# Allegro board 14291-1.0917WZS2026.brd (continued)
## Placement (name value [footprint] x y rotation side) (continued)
C8304  SC10U10V5KX-2GP  [C805H54]  168.09 127.24 180 bottom
C8305  SC1U10V2KX-1GP  [C402H22]  174.03 133.2 180 bottom
C8306  SC470P50V2KX-3GP  [C402H22]  170.86 128.9 0 top
C8307  SC1U10V2KX-1GP  [C402H22]  168.85 133.33 180 bottom
C9101  SC4D7U6D3V3KX-GP  [C603H36]  170.88 21.28 0 bottom
C9102  SCD1U16V2KX-3GP  [C402H22]  171.42 19.6 270 bottom
C9103  SCD1U16V2KX-3GP  [C402H22]  163.57 18.17 90 bottom
C9104  SCD1U16V2KX-3GP  [C402H22]  168.17 30.71 0 bottom
C9105  SCD1U16V2KX-3GP  [C402H22]  160.88 28.67 180 bottom
C9106  SC4D7U6D3V3KX-GP  [C603H36]  161.95 28.56 180 bottom
C9201  SCD1U16V2KX-3GP  [C402H22]  182.48 124.94 0 top
C9202  SC1U10V2KX-1GP  [C402H22]  181.57 124.94 0 top
CPU1  SKYLAKE-U-GP  [BGA1356M4224-U2H52]  115.4 83.77 0 bottom
D502  AZ5725-01FDR7G-GP  [SOD882-10D6-1H20]  148.26 66.99 180 top
D1217  AZ5725-01FDR7G-GP  [SOD882-10D6-1H20]  72.62 30 0 top
D1319  AZ5725-01FDR7G-GP  [SOD882-10D6-1H20]  86.51 17.53 0 top
D1701  1N4148WS-7-F-GP  [SOD323AKH42]  150.31 43.64 270 top
D1702  BAW56-9-GP  [SOT-23-10H44]  153.23 71.02 90 top
D1703  RB751V-40H-GP  [SOD323AKH38]  161.36 66.26 90 top
D2402  RB751V-40H-GP  [SOD323AKH38]  184.48 83.7 180 bottom
D2403  RB751V-40H-GP  [SOD323AKH38]  186.58 85.35 0 bottom
D2405  RB751V-40H-GP  [SOD323AKH38]  167.65 60.48 270 top
D2501  BAS40C-2-GP  [SOT-23-9H44]  51 9.25 180 bottom
D2601  RB551V30-GP  [SOD323AKH38]  97.18 134.35 180 top
D2701  BAT54C-7-F-3-GP  [SOT23-2D4-312H48]  35.09 22.61 90 top
D4001  RB751V-40H-GP  [SOD323AKH38]  30.68 58.17 180 top
D4002  BAS16-6-GP  [SOT23-2D4-312H44]  123.44 150.27 270 top
D4004  1N4148WS-7-F-GP  [SOD323AKH42]  166.2 118.53 270 bottom
D4005  1N4148WS-7-F-GP  [SOD323AKH42]  157.15 113.42 270 bottom
D4304  LBAV99LT1G-1-GP  [SOT23-2D4-312H44]  152.78 168.94 0 top
D4305  LBAV99LT1G-1-GP  [SOT23-2D4-312H44]  156.84 168.94 0 top
D4306  LBAV99LT1G-1-GP  [SOT23-2D4-312H44]  160.9 168.94 0 top
D5401  BAW56-9-GP  [SOT-23-10H44]  15.95 76.23 90 top
D5502  BAT54C-7-F-3-GP  [SOT23-2D4-312H48]  83.78 147.93 270 bottom
D5503  BAT54C-7-F-3-GP  [SOT23-2D4-312H48]  66.42 161.95 90 bottom
D7301  BAT54A-1-GP  [SOT23-2D4-312H44]  184.68 125.89 180 bottom
D7601  1SS400GPT-GP  [SOD723AKH27]  205.79 132.99 90 top
D7602  1SS400GPT-GP  [SOD723AKH27]  205.8 131.7 90 top
D8301  BAT54C-7-F-3-GP  [SOT23-2D4-312H48]  150.04 39.68 180 top
DB1  FOX-CON10-S1-GP  [HS81100]  164.97 33.94 180 bottom
DB2  ACES-CON4-37-GP  [88459-047N]  151.74 9.4 270 bottom
DB3  ACES-CON6-58-GP  [50696-00601-001]  157.09 11.93 180 bottom
DCIN1  ACES-CON6-63-GP  [50458-00601-W01]  91.4 166.77 180 top
DM1  DDR3-204P-252-GP-U  [DAN06-K4406-0103-U]  94.9 34.07 180 bottom
DM2  DDR3-204P-259-GP  [AS0A621-J4SB-7H]  109.4 20.87 0 bottom
EC1001  SC1U10V2KX-1GP  [C402H22]  121.72 14.23 0 top
EC1002  SCD1U25V2KX-GP  [C402H22]  108.97 38.57 0 top
EC1003  SC1U10V2KX-1GP  [C402H22]  111.72 38.59 0 top
EC1004  SC1U10V2KX-1GP  [C402H22]  107.63 29.25 180 top
EC1005  SCD1U25V2KX-GP  [C402H22]  109.52 29.24 180 top
EC1702  SC1KP50V2KX-1GP  [C402H22]  141.39 96.26 180 bottom
EC1703  SC1KP50V2KX-1GP  [C402H22]  156.1 73.6 180 bottom
EC1704  SC1KP50V2KX-1GP  [C402H22]  170.93 77.27 270 top
EC1706  SC1KP50V2KX-1GP  [C402H22]  135.3 102.07 0 bottom
EC1707  SCD1U16V2KX-3GP  [C402H22]  158.92 64.46 180 bottom
EC1708  SCD1U16V2KX-3GP  [C402H22]  96.11 99.06 270 bottom
EC1709  SCD1U16V2KX-3GP  [C402H22]  93 104.39 180 bottom
EC1710  SC22P50V2JN-4GP  [C402H22]  85.92 95.88 180 bottom
EC1711  SCD1U16V2KX-3GP  [C402H22]  149.88 71.64 0 bottom
EC1712  SCD1U16V2KX-3GP  [C402H22]  151.14 74.61 270 bottom
EC1713  SC22P50V2JN-4GP  [C402H22]  138.07 56.66 180 top
EC1801  SC10P50V2JN-4GP  [C402H22]  135.54 64.33 0 top
EC1802  SC10P50V2JN-4GP  [C402H22]  133.01 64.42 180 top
EC1803  SC4D7P50V2BN-GP  [C402H22]  128.11 64.34 180 top
EC1805  SCD1U16V2KX-3GP  [C402H22]  139.76 94.97 270 bottom
EC1806  SCD1U16V2KX-3GP  [C402H22]  134.92 61.46 180 top
EC1807  SCD1U16V2KX-3GP  [C402H22]  135.84 61.46 180 top
EC1808  SCD1U16V2KX-3GP  [C402H22]  138.59 60.14 0 top
EC1901  SC10P50V2JN-4GP  [C402H22]  136.95 45.67 90 bottom
EC1902  SCD1U16V2KX-3GP  [C402H22]  136.95 47.55 270 bottom
EC1903  SC1KP50V2KX-1GP  [C402H22]  135.46 98.71 0 bottom
EC2002  SC1KP50V2KX-1GP  [C402H22]  150.58 89.37 270 top
EC2401  SCD1U16V2KX-3GP  [C402H22]  192.84 72.77 270 top
EC2501  SC4D7P50V2BN-GP  [C402H22]  139.66 53.15 270 top
EC2502  SC4D7P50V2BN-GP  [C402H22]  147.49 54.32 270 bottom
EC2503  SC10P50V2JN-4GP  [C402H22]  139.02 55.35 270 top
EC2504  SC4D7P50V2BN-GP  [C402H22]  156.46 53.9 0 bottom
EC2505  SC10P50V2JN-4GP  [C402H22]  145.36 45.6 90 bottom
EC2506  SC4D7P50V2BN-GP  [C402H22]  145.36 43.9 90 bottom
EC2601  SCD1U16V2KX-3GP  [C402H22]  98.72 139.25 90 top
EC2602  SC10P50V2JN-4GP  [C402H22]  98.36 146.4 90 top
EC2701  SC10P50V2JN-4GP  [C402H22]  33.09 12.58 90 top
EC2703  SCD1U25V2KX-GP  [C402H22]  25 26.05 180 top
EC2704  SC1KP50V2KX-1GP  [C402H22]  16.23 19.71 270 top
EC2705  SCD1U25V2KX-GP  [C402H22]  29.33 27.08 0 bottom
EC2706  SC1KP50V2KX-1GP  [C402H22]  16.23 18.22 270 top
EC2707  SC1KP50V2KX-1GP  [C402H22]  24.89 27.08 0 bottom
EC2708  SC22P50V2JN-4GP  [C402H22]  36.44 19.77 0 top
EC2709  SC22P50V2JN-4GP  [C402H22]  35.94 17.17 180 top
EC2901  SC1KP50V2KX-1GP  [C402H22]  38.2 8.07 180 top
EC2902  SC1KP50V2KX-1GP  [C402H22]  38.41 10.14 0 top
EC2903  SC1KP50V2KX-1GP  [C402H22]  39.54 11.49 180 top
EC2904  SC1KP50V2KX-1GP  [C402H22]  40.36 14.42 0 top
EC2905  SC100P50V2JN-3GP  [C402H22]  21.28 11.01 0 top
EC2906  SC100P50V2JN-3GP  [C402H22]  16.66 11.1 90 top
EC2907  SC100P50V2JN-3GP  [C402H22]  18.21 21.14 90 top
EC2908  SC100P50V2JN-3GP  [C402H22]  17.93 19.61 90 top
EC3101  SC10P50V2JN-4GP  [C402H22]  36.88 175.67 0 top
EC3102  SC10P50V2JN-4GP  [C402H22]  36.88 173.97 180 top
EC3103  SC10P50V2JN-4GP  [C402H22]  35.31 174.34 0 top
EC3104  SC10P50V2JN-4GP  [C402H22]  35.31 172.67 180 top
EC3105  SC10P50V2JN-4GP  [C402H22]  36.83 173.9 0 bottom
EC3106  SC10P50V2JN-4GP  [C402H22]  36.82 175.59 180 bottom
EC3107  SC10P50V2JN-4GP  [C402H22]  35.43 175.8 0 bottom
EC3108  SC10P50V2JN-4GP  [C402H22]  35.43 177.58 180 bottom
EC4001  SCD1U16V2KX-3GP  [C402H22]  155.77 131.36 0 bottom
EC4301  SC10U25V5KX-GP  [C805H56]  90.9 159.15 90 top
EC4302  SCD1U25V2KX-GP  [C402H22]  90.95 157.81 90 top
EC4303  SCD1U25V2KX-GP  [C402H22]  84.49 154.39 270 top
EC4304  SCD1U25V2KX-GP  [C402H22]  96.88 159.41 180 top
EC4306  SC10P50V2JN-4GP  [C402H22]  152.65 166.4 90 top
EC4307  SCD1U25V2KX-GP  [C402H22]  164.21 171.48 90 top
EC4308  SC1U25V3KX-1-GP  [C603H36]  164.33 172.62 90 top
EC4309  SC10P50V2JN-4GP  [C402H22]  160.4 166.4 270 top
EC4310  SC10P50V2JN-4GP  [C402H22]  156.46 166.4 270 top
EC4311  SCD1U25V2KX-GP  [C402H22]  129.94 175.31 90 bottom
EC4312  SCD1U25V2KX-GP  [C402H22]  129.94 170.78 90 bottom
EC4313  SCD1U25V2KX-GP  [C402H22]  142.03 176.81 180 top
EC4314  SCD1U25V2KX-GP  [C402H22]  137.04 176.8 180 top
EC5101  SCD1U50V3KX-GP  [C603H36]  71.3 24.22 270 bottom
EC5102  SC1KP50V2KX-1GP  [C402H22]  100.88 14.25 0 top
EC5103  SC1KP50V2KX-1GP  [C402H22]  134.31 14.28 0 top
EC5301  SCD1U25V2KX-GP  [C402H22]  142.55 136.15 0 top
EC5501  SC6P50V2CN-1GP  [C402H22]  82.56 161.83 90 top
EC5502  SC6P50V2CN-1GP  [C402H22]  80.84 161.84 270 top
EC5503  SC33P50V2JN-3GP  [C402H22]  75.88 162.44 90 bottom
EC5504  SC10P50V2JN-4GP  [C402H22]  89.76 149.64 180 bottom
EC5505  SCD1U25V2KX-GP  [C402H22]  96.16 151.74 90 top
EC6001  SC1KP50V2KX-1GP  [C402H22]  184.83 28.61 90 bottom
EC6102  SC33P50V2JN-3GP  [C402H22]  165.3 65.66 270 bottom
EC6103  SC33P50V2JN-3GP  [C402H22]  163.6 65.66 90 bottom
EC6401  SC1KP50V2KX-1GP  [C402H22]  217.37 152.33 90 top
EC6402  SCD1U25V2KX-GP  [C402H22]  184.65 110.14 270 bottom
EC6403  SCD1U25V2KX-GP  [C402H22]  184.65 106.58 270 bottom
EC6405  SCD1U16V2KX-3GP  [C402H22]  218.82 151.44 270 top
EC6406  SCD1U16V2KX-3GP  [C402H22]  184.12 119.69 90 bottom
EC6407  SCD1U16V2KX-3GP  [C402H22]  183.45 121.48 180 bottom
EC6501  SC33P50V2JN-3GP  [C402H22]  52.19 78.52 0 top
EC6502  SC33P50V2JN-3GP  [C402H22]  49.65 74.32 0 top
EC6503  SC33P50V2JN-3GP  [C402H22]  52.19 80.29 180 top
EC6504  SC33P50V2JN-3GP  [C402H22]  49.65 76.1 180 top
EC6505  SC33P50V2JN-3GP  [C402H22]  49.78 69.88 0 top
EC6506  SC33P50V2JN-3GP  [C402H22]  49.78 71.66 180 top
EC6507  SCD1U16V2KX-3GP  [C402H22]  197.24 116.67 90 bottom
EC9201  SC22P50V2JN-4GP  [C402H22]  178.41 126.48 270 top
EC9202  SC22P50V2JN-4GP  [C402H22]  176.71 126.48 90 top
EC9701  SCD1U25V2KX-GP  [C402H22]  57.25 30.18 90 top
EC9702  SCD1U25V2KX-GP  [C402H22]  49.55 55.5 270 top
EC9703  SCD1U25V2KX-GP  [C402H22]  75.58 70.84 90 top
EC9704  SCD1U25V2KX-GP  [C402H22]  91.08 110.47 90 top
EC9705  SCD1U25V2KX-GP  [C402H22]  141.19 149.79 270 bottom
EC9706  SCD1U25V2KX-GP  [C402H22]  103.95 120.45 270 bottom
EC9707  SCD1U25V2KX-GP  [C402H22]  103.17 130.33 90 top
EC9708  SCD1U25V2KX-GP  [C402H22]  103.18 133.32 90 top
EC9709  SCD1U25V2KX-GP  [C402H22]  119.82 136.04 0 top
EC9710  SCD1U25V2KX-GP  [C402H22]  75.64 80.72 90 top
EC9711  SCD1U25V2KX-GP  [C402H22]  23.71 58.39 270 top
EC9712  SCD1U25V2KX-GP  [C402H22]  214.77 100.03 270 top
EC9713  SCD1U25V2KX-GP  [C402H22]  203.77 100.42 90 top
EC9714  SCD1U25V2KX-GP  [C402H22]  104 126.46 270 bottom
EC9715  SCD1U25V2KX-GP  [C402H22]  140.83 152.36 270 bottom
EC9716  SCD1U25V2KX-GP  [C402H22]  117.86 134.33 270 bottom
EC9717  SCD1U25V2KX-GP  [C402H22]  98.87 130.58 270 top
EC9718  SC1U10V2KX-1GP  [C402H22]  15.05 79.36 180 top
EC9719  SC1U10V2KX-1GP  [C402H22]  43.03 29.47 180 top
EC9720  SC1U10V2KX-1GP  [C402H22]  42.31 25.96 0 top
EC9721  SCD1U25V2KX-GP  [C402H22]  80.85 3.32 180 top
EC9722  SC1U10V2KX-1GP  [C402H22]  198.28 17.55 90 bottom
EC9723  SCD1U25V2KX-GP  [C402H22]  138.99 151.88 0 top
EC9724  SCD1U25V2KX-GP  [C402H22]  108.35 153.49 180 top
EC9725  SC1U10V2KX-1GP  [C402H22]  198.9 45.79 90 top
EC9726  SC1U25V3KX-1-GP  [C603H36]  109.4 153.14 180 top
EC9727  SC1U25V3KX-1-GP  [C603H36]  140.1 152.22 0 top
EC9728  SC1U25V3KX-1-GP  [C603H36]  98.84 131.65 270 top
EC9732  SC1U10V2KX-1GP  [C402H22]  37.28 30.92 90 bottom
EC9733  SC1U10V2KX-1GP  [C402H22]  57.29 11.35 270 bottom
EC9734  SC1U10V2KX-1GP  [C402H22]  148.56 7.52 0 bottom
EC9735  SCD1U25V2KX-GP  [C402H22]  134.75 152.38 180 top
EC9736  SC1U10V2KX-1GP  [C402H22]  36.19 25.9 90 top
EC9737  SC1U10V2KX-1GP  [C402H22]  33.17 75.77 0 bottom
EC9738  SC1U10V2KX-1GP  [C402H22]  67.51 85.75 0 bottom
EC9739  SCD1U25V2KX-GP  [C402H22]  16.28 23.25 270 top
EC9743  SCD1U25V2KX-GP  [C402H22]  16.25 23.27 90 bottom
EC9744  SCD1U25V2KX-GP  [C402H22]  16.63 15.52 0 bottom
EC9745  SC1KP50V2KX-1GP  [C402H22]  14.73 15.4 0 bottom
ED301  AZ5125-01H-R7G-GP  [SOD-523-4H28]  15.45 15.39 180 top
ED302  AZ5125-01H-R7G-GP  [SOD-523-4H28]  18.87 8.74 0 top
ED303  AZ5125-01H-R7G-GP  [SOD-523-4H28]  13.61 8.77 0 top
ED304  AZ5125-01H-R7G-GP  [SOD-523-4H28]  13.65 15.39 180 top
ED305  AZ5125-01H-R7G-GP  [SOD-523-4H28]  17.25 15.39 180 top
ED306  AZ5125-01H-R7G-GP  [SOD-523-4H28]  15.43 8.77 0 top
ED6401  AZ5725-01FDR7G-GP  [SOD882-10D6-1H20]  217.37 153.19 90 top
EU3404  AZC099-04S-2-GP  [SOT-6H58]  179.32 28.6 90 bottom
EU3601  AZC099-04S-2-GP  [SOT-6H58]  16.44 38.95 90 bottom
EU3602  AZC099-04S-2-GP  [SOT-6H58]  22.33 29.32 270 top
EU5701  RCLAMP0524P-2-GP  [SLP2510P8-3H26]  12.37 61.71 90 bottom
EU5702  RCLAMP0524P-2-GP  [SLP2510P8-3H26]  12.49 65.87 90 bottom
EU5703  RCLAMP0524P-2-GP  [SLP2510P8-3H26]  12.08 70.1 90 top
F5502  POLYSW-1D1A24V-GP-U  [POLYSW-4633-UH43]  70.86 159.8 180 bottom
F5503  POLYSW-1D1A24V-GP-U  [POLYSW-4633-UH43]  97.84 150.58 90 bottom
F5701  POLYSW-1D1A6V-9-GP-U  [POLYSW-2114H30]  19.55 72.8 90 bottom
FAN1  ACES-CON4-17-GP-U1  [88631-00401-W01]  90.77 141.43 270 top
FAN261  AP2113MTR-G1-GP  [SOIC8H69]  91.51 138.26 270 bottom
FPR1  PTWO-CON6-21-GP  [196415-06031-3]  179.5 134.99 90 top
G1901  GAP-OPEN  [CON2O-U]  137.06 61.83 0 top
G6401  GAP-OPEN  [CON2O-U]  215.39 149.53 0 bottom
G6402  GAP-OPEN  [CON2O-U]  217.16 151.08 270 top
GPU1  N14M-GE-S-A2-GP  [BGA595M23H83]  192.75 142.67 90 bottom
H1  HOLE256R126-1-GP  [HOLE256R126]  139.3 165.77 0 top
H2  HOLE335R115-GP  [HOLE335R115]  166.9 12.77 0 top
H3  HT85BE95R29-U-5-GP  [HT85BE95R29-U-5]  18.2 50.77 180 bottom
H4  HOLE335R115-GP  [HOLE335R115]  92.4 128.97 0 top
H5  HOLE335R115-GP  [HOLE335R115]  35 164.77 0 top
H6  HOLE256R126-1-GP  [HOLE256R126]  197.1 56.27 0 top
H7  HOLE296R182-GP  [HOLE296R182]  151.5 60.97 0 top
HCPU1  HOLE197R166-1-GP  [HOLE197R166]  88.2 70.77 0 top
HCPU2  HOLE197R166-1-GP  [HOLE197R166]  142.6 70.77 0 top
HCPU3  HOLE197R166-1-GP  [HOLE197R166]  115.4 102.77 0 top
HDA27  ALC3246-CG-GP-U  [QFN48J6-G465H40]  27.35 15.87 270 top
HDD1  ACES-CON20-28-GP  [50406-02071-001]  190.6 28.77 90 bottom
HDMI1  SKT-HDMI23-92-GP  [SKT-HDMI23-188137]  1.75 66.67 90 bottom
HGPU1  STF237R117H81-1-GP  [STF237R117H81]  162.7 132.69 0 bottom
HGPU2  STF237R117H81-1-GP  [STF237R117H81]  217.09 142.69 0 bottom
HGPU3  STF237R117H81-1-GP  [STF237R117H81]  162.7 152.69 0 bottom
HPMIC1  PAD-AUDIO-JK509-GP-U-1  [PAD-2SJ3095-060111F-U-1]  1.5 7.87 90 bottom
IOBD1  ACES-CON18-2-GP  [88513-180N-W01]  189.9 33.27 90 top
IRCCD1  ACES-CON6-19-GP-U  [50208-0060N-001]  91.7 151.77 270 top
KB1  ACES-CON30-10-GP  [FL4S030HT6R300-DT]  184.45 105.85 270 top
KBC24  MEC1404-NU-GP  [TQFP128-2H48]  181.48 74.41 270 top
KBLIT1  ACES-CON4-56-GP-U  [51575-00401-W01]  197.5 94.92 90 top
L2901  PBY160808T-121Y-GP  [L1608-UH38]  39.85 8.13 270 top
L2902  PBY160808T-121Y-GP  [L1608-UH38]  40.01 9.45 270 top
L2903  PBY160808T-121Y-GP  [L1608-UH38]  41.14 12.5 270 top
L2904  PBY160808T-121Y-GP  [L1608-UH38]  41.98 13.82 270 top
L7301  MHC1608S121PBP-GP  [L603H38]  182.6 146.23 180 top
L7501  MHC1608S300QBP-GP  [L603H38]  187.93 146.71 270 top
L7601  MHC1608S300QBP-GP  [L603H38]  196.95 133.1 180 top
L7602  MCB1608S181FBP-GP  [L603H38]  195.4 131.25 270 top
LCD1  ACES-CON40-18-GP  [51540-04001-W01]  74.9 167.57 270 top
LEDBD1  PTWO-CON6-21-GP  [196415-06031-3]  194.9 124.37 90 top
LOM31  RTL8111G-CGT-1-GP-U2  [QFN32J4-G2D85H36]  46.53 168.97 90 top
MESW1  SW-SLIDE6P-6-GP  [JSD1210-0111FC]  179.21 9.34 180 bottom
NOREF  -  []  226.25 78.02 0 top
NOREF#2  -  []  -132.68 247.99 0 top
NOREF#3  -  []  211.65 48.66 90 top
NOREF#4  -  []  1.9 -48.23 0 top
NOREF#5  *  [unnamed#2]  197.38 5.82 0 top
NOREF#6  -  []  -6.8 122.74 90 top
NOREF#7  -  []  127.18 9.4 0 top
NOREF#8  -  [unnamed#2]  221.26 3.18 0 top
NOREF#9  -  [unnamed#2]  215.51 6.38 0 top
NOREF#10  -  [unnamed#2]  62.73 96.99 0 top
NOREF#11  -  [unnamed#2]  145.7 163.97 0 top
NOREF#12  -  [unnamed#2]  215.01 82.33 0 top
NOREF#13  *  [unnamed#2]  220.99 11.92 0 top
NOREF#14  -  []  1.9 -48.23 0 top
NOREF#15  -  [unnamed#2]  -5.39 -0.19 0 top
NOREF#16  *  [unnamed#2]  5.81 -1.43 0 top
NOREF#17  -  []  1.9 -48.23 0 top
NOREF#18  -  [unnamed#2]  75.65 153.1 0 top
NOREF#19  *  [unnamed#2]  -5.39 182.28 0 top
NOREF#20  -  [unnamed#2]  117.18 185.87 0 top
NOREF#21  *  [unnamed#2]  13.49 178.81 0 top
NOREF#22  -  [unnamed#2]  -4.35 156.08 0 top
NOREF#23  -  []  1.9 -48.23 0 top
NOREF#24  -  []  1.9 -48.23 0 top
NOREF#25  *  [unnamed#2]  9.06 79.23 0 top
NOREF#26  -  []  91.64 180.32 180 top
NOREF#27  -  []  117.32 50.87 0 top
NOREF#28  -  []  1.9 -48.23 0 top
NOREF#29  -  [unnamed#2]  3.39 79.07 0 top
NOREF#30  -  []  193.16 5.11 0 top
NOREF#31  -  []  461.57 -47.77 180 bottom
NOREF#32  *  [unnamed#2]  9.06 79.23 180 bottom
NOREF#33  *  [unnamed#2]  197.38 5.82 180 bottom
NOREF#34  *  [unnamed#2]  -5.39 182.28 180 bottom
NOREF#35  -  []  209.43 177.44 180 bottom
NOREF#36  *  [unnamed#2]  220.99 11.92 180 bottom
NOREF#37  -  []  79.89 70.1 180 bottom
NOREF#38  *  [unnamed#2]  5.81 -1.43 180 bottom
NOREF#39  *  [unnamed#2]  13.49 178.81 180 bottom
NOREF#40  -  []  100.71 0.23 180 bottom
PC1001  SC22U6D3V3MX-1-GP  [C603H40]  110.93 86.43 270 top
PC1002  SC22U6D3V3MX-1-GP  [C603H40]  110.19 84.4 270 top
PC1003  SC22U6D3V3MX-1-GP  [C603H40]  130.39 109.24 90 top
PC1004  SC22U6D3V3MX-1-GP  [C603H40]  130.39 110.54 90 top
PC1005  SC22U6D3V3MX-1-GP  [C603H40]  130.4 117 90 top
PC1006  SC22U6D3V3MX-1-GP  [C603H40]  130.4 118.28 90 top
PC1007  SC22U6D3V3MX-1-GP  [C603H40]  130.39 119.55 90 top
PC1008  SC22U6D3V3MX-1-GP  [C603H40]  117.24 82.7 90 top
PC1009  SC22U6D3V3MX-1-GP  [C603H40]  120.17 119.44 270 top
PC1010  SC22U6D3V3MX-1-GP  [C603H40]  120.17 118.15 270 top
PC1011  SC22U6D3V3MX-1-GP  [C603H40]  120.17 116.85 270 top
PC1012  SC22U6D3V3MX-1-GP  [C603H40]  120.17 110.33 90 bottom
PC1013  SC22U6D3V3MX-1-GP  [C603H40]  110.11 81.85 270 top
PC1014  SC22U6D3V3MX-1-GP  [C603H40]  110.19 83.13 270 top
PC1015  SC22U6D3V3MX-1-GP  [C603H40]  120.17 115.53 270 top
PC1016  SC22U6D3V3MX-1-GP  [C603H40]  120.17 114.24 270 top
PC1017  SC22U6D3V3MX-1-GP  [C603H40]  120.17 112.92 270 top
PC1018  SC22U6D3V3MX-1-GP  [C603H40]  130.39 111.83 90 top
PC1019  SC22U6D3V3MX-1-GP  [C603H40]  117.25 83.99 90 top
PC1020  SC22U6D3V3MX-1-GP  [C603H40]  120.17 111.62 270 top
PC1021  SC22U6D3V3MX-1-GP  [C603H40]  118.18 87.71 90 top
PC1022  SC22U6D3V3MX-1-GP  [C603H40]  114.53 88.74 90 top
PC1023  SC22U6D3V3MX-1-GP  [C603H40]  128.44 109.76 270 bottom
PC1024  SC22U6D3V3MX-1-GP  [C603H40]  120.17 110.33 270 top
PC1025  SC22U6D3V3MX-1-GP  [C603H40]  129.53 118.9 270 bottom
PC1026  SC22U6D3V3MX-1-GP  [C603H40]  130.39 113.13 90 top
PC1027  SC22U6D3V3MX-1-GP  [C603H40]  130.39 114.42 90 top
PC1028  SC22U6D3V3MX-1-GP  [C603H40]  130.39 115.72 90 top
PC1029  SC22U6D3V3MX-1-GP  [C603H40]  128.44 108.36 270 bottom
PC1030  SC22U6D3V3MX-1-GP  [C603H40]  120.17 111.62 90 bottom
PC1031  SC22U6D3V3MX-1-GP  [C603H40]  85.63 90.61 270 top
PC1032  SC22U6D3V3MX-1-GP  [C603H40]  96.51 114.61 270 top
PC1033  SC22U6D3V3MX-1-GP  [C603H40]  115.9 115.26 270 bottom
PC1034  SC22U6D3V3MX-1-GP  [C603H40]  85.63 82.99 270 top
PC1035  SC22U6D3V3MX-1-GP  [C603H40]  156.29 122.75 0 bottom
PC1036  SC22U6D3V3MX-1-GP  [C603H40]  154.89 122.75 0 bottom
PC1037  SC22U6D3V3MX-1-GP  [C603H40]  153.5 122.75 0 bottom
PC1038  SC22U6D3V5MX-2GP  [C805H58]  155.69 117.7 270 bottom
PC1039  SC22U6D3V5MX-2GP  [C805H58]  155.69 115.87 270 bottom
PC1041  SC22U6D3V3MX-1-GP  [C603H40]  107.61 88.42 0 top
PC1042  SC22U6D3V3MX-1-GP  [C603H40]  108.88 88.42 0 top
PC1043  SC22U6D3V3MX-1-GP  [C603H40]  110.15 88.27 0 top
PC1044  SC22U6D3V3MX-1-GP  [C603H40]  104.26 81.74 0 top
PC1046  SC22U6D3V3MX-1-GP  [C603H40]  134.35 113.83 90 bottom
PC1047  SC22U6D3V3MX-1-GP  [C603H40]  134.35 115.1 90 bottom
PC1048  SC22U6D3V3MX-1-GP  [C603H40]  139.31 114.96 270 bottom
PC1049  SC22U6D3V3MX-1-GP  [C603H40]  139.31 113.57 270 bottom
PC1050  SC22U6D3V3MX-1-GP  [C603H40]  134.36 111.28 90 bottom
PC1051  SC22U6D3V3MX-1-GP  [C603H40]  134.35 112.56 90 bottom
PC1052  SC22U6D3V3MX-1-GP  [C603H40]  139.3 112.42 90 top
PC1053  SC22U6D3V3MX-1-GP  [C603H40]  134.35 115.1 270 top
PC1054  SC22U6D3V3MX-1-GP  [C603H40]  120.51 87.65 0 top
PC1055  SC10U6D3V3MX-GP  [C603H38]  90.22 62.36 270 top
PC1056  SC10U6D3V3MX-GP  [C603H38]  89.1 55.66 270 top
PC1057  SC10U6D3V3MX-GP  [C603H38]  97.93 63.98 90 top
PC1058  SC10U6D3V3MX-GP  [C603H38]  109.52 63.96 90 top
PC1059  SC10U6D3V3MX-GP  [C603H38]  119.08 38.4 0 top
PC1060  SC10U6D3V3MX-GP  [C603H38]  119.03 72.79 90 top
PC1061  SC10U6D3V3MX-GP  [C603H38]  114.75 72.8 90 top
PC1062  SC22U6D3V3MX-1-GP  [C603H40]  119.44 64.58 270 top
PC1063  SC22U6D3V3MX-1-GP  [C603H40]  89.1 54.39 270 top
PC1064  SC22U6D3V5MX-2GP  [C805H58]  90.24 60.74 270 top
PC1065  SC22U6D3V3MX-1-GP  [C603H40]  119.75 82.33 180 top
PC1066  SC22U6D3V3MX-1-GP  [C603H40]  134.35 111.29 270 top
PC1067  SC22U6D3V3MX-1-GP  [C603H40]  139.31 113.69 90 top
PC1068  SC22U6D3V3MX-1-GP  [C603H40]  139.31 114.96 90 top
PC1069  SC22U6D3V3MX-1-GP  [C603H40]  96.51 107.62 270 top
PC1070  SC22U6D3V3MX-1-GP  [C603H40]  96.55 106.3 270 top
PC1071  SC22U6D3V3MX-1-GP  [C603H40]  96.54 104.98 270 top
PC1072  SC22U6D3V3MX-1-GP  [C603H40]  96.51 103.64 270 top
PC1073  SC22U6D3V3MX-1-GP  [C603H40]  115.9 113.86 90 top
PC1074  SC22U6D3V3MX-1-GP  [C603H40]  96.51 102.24 270 top
PC1075  SC22U6D3V3MX-1-GP  [C603H40]  85.63 93.15 270 top
PC1076  SC22U6D3V3MX-1-GP  [C603H40]  96.51 113.21 270 top
PC1077  SC22U6D3V3MX-1-GP  [C603H40]  85.63 86.8 270 top
PC1078  SC22U6D3V3MX-1-GP  [C603H40]  85.63 88.07 270 top
PC1079  SC22U6D3V3MX-1-GP  [C603H40]  85.63 89.34 270 top
PC1080  SC22U6D3V3MX-1-GP  [C603H40]  85.63 91.88 270 top
PC1081  SC22U6D3V3MX-1-GP  [C603H40]  85.63 81.72 270 top
PC1082  SC22U6D3V3MX-1-GP  [C603H40]  96.51 111.82 270 top
PC1083  SC22U6D3V3MX-1-GP  [C603H40]  96.51 110.42 270 top
PC1084  SC22U6D3V3MX-1-GP  [C603H40]  96.51 109.02 270 top
PC1085  SC22U6D3V3MX-1-GP  [C603H40]  115.9 115.26 90 top
PC1086  SC22U6D3V3MX-1-GP  [C603H40]  115.9 116.65 90 top
PC1087  SC22U6D3V3MX-1-GP  [C603H40]  85.63 85.53 270 top
PC1088  SC22U6D3V3MX-1-GP  [C603H40]  115.9 118.05 270 bottom
PC1089  SC22U6D3V3MX-1-GP  [C603H40]  107.11 85.29 90 top
PC1090  SC22U6D3V3MX-1-GP  [C603H40]  85.63 84.26 270 top
PC1091  SC22U6D3V3MX-1-GP  [C603H40]  115.9 116.65 270 bottom
PC1092  SC22U6D3V3MX-1-GP  [C603H40]  107.11 84 90 top
PC1093  SC22U6D3V3MX-1-GP  [C603H40]  115.9 118.05 90 top
PC1094  SC22U6D3V3MX-1-GP  [C603H40]  115.9 113.86 270 bottom
PC1095  SC22U6D3V3MX-1-GP  [C603H40]  107.11 82.7 90 top
PC1096  SC22U6D3V3MX-1-GP  [C603H40]  106.95 86.59 90 top
PC1097  SC22U6D3V3MX-1-GP  [C603H40]  134.35 113.83 270 top
PC1098  SC22U6D3V3MX-1-GP  [C603H40]  134.35 112.56 270 top
PC4301  SC1U50V5ZY-1-GP-U  [C805H58]  88.5 152.87 90 bottom
PC4302  SCD1U50V3KX-GP  [C603H36]  96.13 154.69 270 bottom
PC4303  SCD01U50V2KX-1GP  [C402H22]  101.7 159.95 180 top
PC4304  SCD01U50V2KX-1GP  [C402H22]  100.88 159.95 180 top
PC4305  SCD01U50V2KX-1GP  [C402H22]  100.07 159.95 180 top
PC4306  SC10U25V5KX-GP  [C805H56]  98.75 159.97 180 top
PC4308  SC1U25V3KX-1-GP  [C603H36]  111.5 171.23 180 top
PC4309  SCD01U50V2KX-1GP  [C402H22]  116.58 171.23 180 top
PC4310  SCD47U6D3V2KX-GP  [C402H22]  119.25 171.23 0 top
PC4401  SC2D2U10V3KX-1GP  [C603H36]  111 163.69 270 top
PC4402  SCD1U25V2KX-GP  [C402H22]  109.85 155.86 90 bottom
PC4403  SCD1U25V2KX-GP  [C402H22]  109.47 154.08 0 bottom
PC4404  SCD1U25V2KX-GP  [C402H22]  110.36 154.08 0 bottom
PC4405  SC10U25V5KX-GP  [C805H56]  117.98 159.41 180 top
PC4406  SC10U25V5KX-GP  [C805H56]  116.07 159.41 180 top
PC4407  SC10U25V5KX-GP  [C805H56]  117.98 159.41 0 bottom
PC4408  SC10U25V5KX-GP  [C805H56]  116.07 159.41 0 bottom
PC4409  SCD1U50V3KX-GP  [C603H36]  114.42 159.29 0 bottom
PC4410  SC2200P50V2KX-2GP  [C402H22]  119.37 159.41 180 top
PC4411  SCD1U25V2KX-GP  [C402H22]  119.37 159.41 0 bottom
PC4412  SC1U25V3KX-1-GP  [C603H36]  111.48 156.87 0 bottom
PC4413  SCD01U50V2KX-1GP  [C402H22]  105.7 155.59 180 bottom
PC4414  SCD047U25V2KX-GP  [C402H22]  111.31 159.76 180 bottom
PC4415  SC10U25V5KX-GP  [C805H56]  129.92 175.42 270 top
PC4416  SC10U25V5KX-GP  [C805H56]  129.92 173.51 270 top
PC4417  SC10U25V5KX-GP  [C805H56]  129.92 171.61 270 top
PC4418  SC10U25V5KX-GP  [C805H56]  129.92 169.7 270 top
PC4419  SCD1U50V3KX-GP  [C603H36]  130.04 168.05 270 top
PC4420  SCD1U25V2KX-GP  [C402H22]  107.69 166.53 90 bottom
PC4421  SCD1U25V2KX-GP  [C402H22]  108.2 168.43 0 bottom
PC4422  SCD1U25V2KX-GP  [C402H22]  107.31 168.43 0 bottom
PC4423  SC100P50V3JN-2GP  [C603H36]  100.75 155.21 90 bottom
PC4424  SC100P50V3JN-2GP  [C603H36]  99.31 156.87 90 bottom
PC4426  SC1U25V3KX-1-GP  [C603H36]  124.57 167.1 90 top
PC4509  SC4D7U25V5KX-GP  [C805H54]  32.41 49.55 270 bottom
PC4516  SCD1U50V3KX-GP  [C603H36]  44.06 54.89 270 top
PC4517  SCD1U16V2KX-3GP  [C402H22]  32.51 32.03 270 top
PC4518  SCD1U16V2KX-3GP  [C402H22]  42.02 31.97 90 top
PC4519  SC10U25V5KX-GP  [C805H56]  36.6 50.82 270 top
PC4520  SC330P50V3KX-GP  [C603]  37.74 45.87 180 top
PC4522  SC18P50V2JN-1-GP  [C402H22]  40.13 58.77 270 top
PC4523  SC18P50V2JN-1-GP  [C402H22]  35.71 59.94 0 top
PC4524  SC1U10V3KX-4GP-U  [C603H36]  39.59 50.62 0 top
PC4525  SCD1U50V3KX-GP  [C603H36]  32.38 47.9 90 top
PC4526  SC4D7U6D3V3KX-GP  [C603H36]  38.91 59.61 90 bottom
PC4527  SC10U25V5KX-GP  [C805H56]  45.11 49.3 90 bottom
PC4528  SC10U25V5KX-GP  [C805H56]  32.41 49.55 90 top
PC4529  SC4D7U25V5KX-GP  [C805H54]  45.11 49.3 270 top
PC4530  SCD1U50V3KX-GP  [C603H36]  45.08 47.65 270 top
PC4531  SCD01U50V2KX-1GP  [C402H22]  38.5 50.95 0 top
PC4535  SCD1U50V3KX-GP  [C603H36]  33.9 54.38 90 top
PC4536  SC560P50V-GP  [C603]  39.77 45.87 180 top
PC4601  SC1500P50V2KX-2GP  [C402H22]  119.81 141.89 270 bottom
PC4602  SCD01U50V2KX-1GP  [C402H22]  113.71 149.38 0 top
PC4603  SC1KP50V2KX-1GP  [C402H22]  112.01 149.38 0 top
PC4604  SC15P50V2JN-2-GP  [C402H22]  113.42 145.39 0 bottom
PC4605  SC1KP50V2KX-1GP  [C402H22]  112.03 150.68 90 top
PC4606  SCD015U25V2KX-GP  [C402H22]  116.43 148.7 90 top
PC4607  SCD01U50V2KX-1GP  [C402H22]  116.84 149.53 90 top
PC4608  SC1KP50V2KX-1GP  [C402H22]  110.31 149.39 0 top
PC4609  SC220P50V2KX-3GP  [C402H22]  115.89 145.39 180 bottom
PC4610  SCD1U25V2KX-GP  [C402H22]  124.57 147.86 90 top
PC4611  SC1KP50V2KX-1GP  [C402H22]  107.67 148.06 270 top
PC4612  SC2200P50V2KX-2GP  [C402H22]  107.67 146.44 90 top
PC4613  SC470P50V2KX-3GP  [C402H22]  117.15 143.64 90 bottom
PC4614  SC470P50V2KX-3GP  [C402H22]  105.28 145.19 180 bottom
PC4615  SC470P50V2KX-3GP  [C402H22]  111.33 144.97 90 bottom
PC4616  SCD056U16V2KX-GP  [C402H22]  119.63 143.13 0 top
PC4617  SC10P50V2JN-4GP  [C402H22]  107.06 144.43 180 bottom
PC4618  SC2200P50V2KX-2GP  [C402H22]  106.67 143.16 270 bottom
PC4619  SC15P50V2JN-2-GP  [C402H22]  116.74 141.9 90 bottom
PC4620  SC1KP50V2KX-1GP  [C402H22]  107.05 143.49 0 top
PC4621  SC100P50V2JN-3GP  [C402H22]  107.93 143.49 0 top
PC4622  SC1KP50V2KX-1GP  [C402H22]  120.06 141.86 270 top
PC4623  SCD047U25V2KX-GP  [C402H22]  108.01 141.55 180 bottom
PC4625  SC1KP50V2KX-1GP  [C402H22]  120.49 139.75 0 top
PC4626  SCD01U50V2KX-1GP  [C402H22]  111.4 143.27 270 bottom
PC4627  SC1KP50V2KX-1GP  [C402H22]  120.92 138.51 90 top
PC4628  SCD1U25V2KX-GP  [C402H22]  117.01 140.64 0 bottom
PC4629  SCD01U50V2KX-1GP  [C402H22]  110.27 140.84 0 bottom
PC4630  SCD1U25V2KX-GP  [C402H22]  111.4 142.38 270 bottom
PC4631  SC1U10V2KX-1GP  [C402H22]  111.09 141.11 0 bottom
PC4632  SC1KP50V2KX-1GP  [C402H22]  114.24 145.39 180 bottom
PC4633  SC1KP50V2KX-1GP  [C402H22]  116.74 142.79 90 bottom
PC4634  SCD022U16V2KX-3GP  [C402H22]  120.52 143.13 0 top
PC4701  SC10U25V5KX-GP  [C805H56]  121.79 133.46 90 bottom
PC4702  SC10U25V5KX-GP  [C805H56]  121.79 135.26 90 bottom
PC4703  SC10U25V5KX-GP  [C805H56]  121.79 135.15 270 top
PC4704  SC10U25V5KX-GP  [C805H56]  121.79 133.35 270 top
PC4705  SC10U25V5KX-GP  [C805H56]  121.79 131.55 270 top
PC4706  SCD22U25V3KX-GP  [C603H40]  125.42 131.78 180 top
PC4707  SC2D2U10V2KX-GP  [C402H22]  127.33 126.69 90 top
PC4708  SC1U10V2KX-1GP  [C402H22]  128.6 127.09 0 top
PC4709  SC2200P50V2KX-2GP  [C402H22]  121.31 127.61 180 top
PC4710  SCD1U25V2KX-GP  [C402H22]  121.71 132.14 90 bottom
PC4802  SC10U25V5KX-GP  [C805H56]  108 132.95 270 top
PC4803  SC10U25V5KX-GP  [C805H56]  108 134.75 270 top
PC4804  SC10U25V5KX-GP  [C805H56]  107.99 132.94 90 bottom
PC4805  SC10U25V5KX-GP  [C805H56]  107.99 134.74 90 bottom
PC4806  SC10U25V5KX-GP  [C805H56]  108 131.14 270 top
PC4807  SC2D2U10V2KX-GP  [C402H22]  114.11 126.05 90 top
PC4808  SC1U10V2KX-1GP  [C402H22]  115.38 126.46 0 top
PC4809  SCD22U25V3KX-GP  [C603H40]  112 131.27 180 top
PC4810  SC2200P50V2KX-2GP  [C402H22]  108.07 126.9 180 top
PC4811  SCD1U25V2KX-GP  [C402H22]  107.99 131.63 90 bottom
PC5001  SC2D2U10V3KX-1GP  [C603H36]  132.54 138.2 0 top
PC5002  SCD1U25V2KX-GP  [C402H22]  135 132.36 90 bottom
PC5008  SCD22U25V3KX-GP  [C603H40]  135.63 134.9 270 top
PC5027  SC10U25V5KX-GP  [C805H56]  134.87 133.13 270 top
PC5029  SC10U25V5KX-GP  [C805H56]  135.05 133.76 90 bottom
PC5031  SC2200P50V2KX-2GP  [C402H22]  132.71 130.08 180 top
PC5101  SC1U10V3KX-4GP-U  [C603H36]  51.15 18.7 90 top
PC5102  SCD01U50V2KX-1GP  [C402H22]  48.49 17.16 0 top
PC5103  SCD1U16V2KX-3GP  [C402H22]  47.6 17.16 0 top
PC5104  SC1U10V3KX-4GP-U  [C603H36]  46.67 24.36 270 bottom
PC5106  SCD1U16V2KX-3GP  [C402H22]  49.94 25.82 180 top
PC5109  SC4D7U25V5KX-GP  [C805H54]  54.99 27.33 0 bottom
PC5111  SC4D7U25V5KX-GP  [C805H54]  56.93 22.66 180 bottom
PC5112  SC10U25V5KX-GP  [C805H56]  53.08 27.33 0 bottom
PC5113  SCD1U50V3KX-GP  [C603H36]  56.34 22.64 180 top
PC5114  SC4D7U25V5KX-GP  [C805H54]  54.73 22.64 0 top
PC5115  SCD1U16V2KX-3GP  [C402H22]  41.39 23.86 180 top
PC5116  SC10U6D3V3MX-GP  [C603H38]  43.84 23.94 180 top
PC5117  SC10U6D3V3MX-GP  [C603H38]  42.44 23.94 180 top
PC5118  SCD22U10V2KX-1GP  [C402H22]  45.88 19.33 90 top
PC5119  SCD1U50V3KX-GP  [C603H36]  52.54 22.74 270 top
PC5120  SC4D7U6D3V3KX-GP  [C603H36]  71.3 22.83 270 bottom
PC5121  SCD1U16V2KX-3GP  [C402H22]  71.3 25.34 270 bottom
PC5122  SC330P50V2KX-3GP  [C402H22]  57.27 16.67 270 top
PC5123  SC22U6D3V5MX-2GP  [C805H58]  71.01 16.39 180 bottom
PC5124  SC22U6D3V5MX-2GP  [C805H58]  71.22 19.37 270 bottom
PC5125  SC22U6D3V5MX-2GP  [C805H58]  71.22 21.27 270 bottom
PC5126  SC22U6D3V5MX-2GP  [C805H58]  69.18 16.39 180 bottom
PC5127  SC22U6D3V5MX-2GP  [C805H58]  65.37 16.39 180 bottom
PC5128  SC22U6D3V5MX-2GP  [C805H58]  67.28 16.39 180 bottom
PC5227  SC22P50V2JN-4GP  [C402H22]  151.12 124.49 270 bottom
PC5301  SC10U25V5KX-GP  [C805H56]  143.53 136.2 180 bottom
PC5302  SC22U6D3V3MX-1-GP  [C603H40]  142.31 123.56 90 bottom
PC5303  SC22U6D3V5MX-2GP  [C805H58]  142.31 118.1 90 bottom
PC5304  SC2D2U10V3KX-1GP  [C603H36]  150.8 137.87 270 bottom
PC5305  SCD1U50V3KX-GP  [C603H36]  146.45 134.8 270 top
PC5306  SC220P50V2KX-3GP  [C402H22]  151.38 135.84 90 bottom
PC5307  SC22U6D3V5MX-2GP  [C805H58]  142.31 121.91 90 bottom
PC5308  SC22U6D3V5MX-2GP  [C805H58]  142.31 120.01 90 bottom
PC5309  SC1U10V2KX-1GP  [C402H22]  151.54 138.94 90 bottom
PC5310  SC10U25V5KX-GP  [C805H56]  141.63 136.2 180 bottom
PC5311  SCD22U10V2KX-1GP  [C402H22]  151.51 133.15 180 bottom
PC5401  SC1U10V3KX-4GP-U  [C603H36]  171.19 112.93 0 bottom
PC5402  SC22U6D3V3MX-1-GP  [C603H40]  167.76 103.66 90 bottom
PC5403  SC10U6D3V3MX-GP  [C603H38]  169.79 112.93 0 bottom
PC5404  SC22U6D3V3MX-1-GP  [C603H40]  167.76 105.57 90 bottom
PC5405  SC68P50V2JN-1GP  [C402H22]  172.21 102.01 270 bottom
PC5406  SC4700P50V2KX-1GP  [C402H22]  174.49 112.17 270 bottom
PC5407  SCD1U16V2KX-3GP  [C402H22]  41.01 20.33 180 top
PC5408  SC1U10V2KX-1GP  [C402H22]  41.98 17.51 180 top
PC5409  SC1U10V2KX-1GP  [C402H22]  38.23 15.34 90 top
PC8201  SCD1U16V2KX-3GP  [C402H22]  208.55 94.29 0 bottom
PC8202  SCD1U25V2KX-GP  [C402H22]  208.4 92.49 0 bottom
PC8203  SC1KP50V2KX-1GP  [C402H22]  213.23 94.16 90 bottom
PC8204  SCD01U50V2KX-1GP  [C402H22]  209.39 93.32 180 bottom
PC8205  SC47P50V2JN-3GP  [C402H22]  206.07 95.13 180 bottom
PC8206  SC330P50V2KX-3GP  [C402H22]  209.93 109.5 180 bottom
PC8207  SCD1U50V3KX-GP  [C603H36]  209.16 102.9 0 bottom
PC8208  SC4D7U25V5KX-GP  [C805H54]  203.07 103.79 270 bottom
PC8209  SC4D7U25V5KX-GP  [C805H54]  203.25 101.85 90 top
PC8210  SC10U25V5KX-GP  [C805H56]  203.07 101.88 270 bottom
PC8211  SCD1U50V3KX-GP  [C603H36]  212.83 100.75 90 bottom
PC8212  SC4D7U25V5KX-GP  [C805H54]  215.51 103.46 90 bottom
PC8213  SC4D7U25V5KX-GP  [C805H54]  215.51 101.6 90 bottom
PC8214  SC10U25V5KX-GP  [C805H56]  203.25 103.76 90 top
PC8215  SC10U25V5KX-GP  [C805H56]  215.51 101.5 270 top
PC8216  SCD1U50V3KX-GP  [C603H36]  203.88 99.45 270 bottom
PC8217  SC47P50V2JN-3GP  [C402H22]  203.63 93.86 180 bottom
PC8218  SC330P50V2KX-3GP  [C402H22]  208.66 109.5 180 bottom
PC8219  SC47P50V2JN-3GP  [C402H22]  204.48 94.58 180 bottom
PC8220  SCD1U25V2KX-GP  [C402H22]  202.94 105.19 90 bottom
PC8221  SCD1U25V2KX-GP  [C402H22]  215.39 104.8 270 bottom
PC8222  SC47P50V2JN-3GP  [C402H22]  203.63 95.64 0 bottom
PC8223  SC2700P50V2KX-1-GP  [C402H22]  211.14 92.5 180 bottom
PC8224  SC10U25V5KX-GP  [C805H56]  215.51 103.41 270 top
PC8225  SCD1U25V2KX-GP  [C402H22]  212.72 97.11 180 bottom
PC8226  SCD1U25V2KX-GP  [C402H22]  213.61 95.41 0 bottom
PC8301  SC1U10V2KX-1GP  [C402H22]  141.98 153.7 90 bottom
PC8302  SC22P50V2GN-GP  [C402H22]  148.18 150.98 180 bottom
PC8303  SC10U6D3V3MX-GP  [C603H38]  157.35 151.41 180 bottom
PC8304  SC10U6D3V3MX-GP  [C603H38]  155.95 151.41 180 bottom
PC8305  SC100P50V2JN-3GP  [C402H22]  142.81 151.08 0 bottom
PC8306  SC10U6D3V3MX-GP  [C603H38]  145.03 156.87 270 bottom
PC8307  SC10U6D3V3MX-GP  [C603H38]  145.03 158.27 270 bottom
PC8308  SCD01U50V2KX-1GP  [C402H22]  156.69 36.09 90 top
PC8309  SC10U6D3V3MX-GP  [C603H38]  148.86 34.94 180 top
PC8310  SC10U6D3V3MX-GP  [C603H38]  160.86 34.73 180 top
PD4301  P6SBMJ24APT-GP  [D5436AKH97]  94.61 159.54 180 bottom
PD4302  LBAV99LT1G-1-GP  [SOT23-2D4-312H44]  125.34 174.4 180 top
PD4303  PESD24VS2UT-GP  [SOT-23-10H44]  103.26 175.98 0 top
PD4304  SMF18AT1G-GP  [SOD123FLAKH40]  164.21 174.65 270 top
PD4402  CH035H-40PT0-GP  [SOD323AKH40]  114.55 163.73 0 top
PD4403  CH035H-40PT0-GP  [SOD323AKH40]  112.75 160.52 180 bottom
PD4404  1N4148WS-7-F-GP  [SOD323AKH42]  119.93 166.42 90 top
PD4405  CH035H-40PT0-GP  [SOD323AKH40]  116.67 163.74 0 top
PG4401  GAP-CLOSE-PWR-3-GP  [GAP-CLOSE-PWR-3]  103.92 155.59 270 bottom
PG4402  GAP-CLOSE-PWR-3-GP  [GAP-CLOSE-PWR-3]  104.56 153.84 90 top
PG4403  GAP-CLOSE-PWR-3-GP  [GAP-CLOSE-PWR-3]  106.03 153.81 90 top
PG4404  -  [GAP-CLOSE-PWR]  119.25 155.6 270 bottom
PG4405  -  [GAP-CLOSE-PWR]  118.49 155.6 270 bottom
PG4406  -  [GAP-CLOSE-PWR]  117.72 155.6 270 bottom
PG4407  -  [GAP-CLOSE-PWR]  116.96 155.6 270 bottom
PG4409  GAP-CLOSE-PWR-3-GP  [GAP-CLOSE-PWR-3]  100.3 160.48 180 bottom
PG4410  GAP-CLOSE-PWR-3-GP  [GAP-CLOSE-PWR-3]  99.83 161.44 180 bottom
PG4411  GAP-CLOSE-PWR-3-GP  [GAP-CLOSE-PWR-3]  107.74 162.82 0 top
PG4412  GAP-CLOSE-PWR-3-GP  [GAP-CLOSE-PWR-3]  130.55 164.24 0 top
PG4413  GAP-CLOSE-PWR-3-GP  [GAP-CLOSE-PWR-3]  130.55 166.02 0 top
PG4414  GAP-CLOSE-PWR-3-GP  [GAP-CLOSE-PWR-3]  101.85 157 180 bottom
PG4415  GAP-CLOSE-PWR-3-GP  [GAP-CLOSE-PWR-3]  101.85 158.02 180 bottom
PG4416  GAP-CLOSE-PWR-3-GP  [GAP-CLOSE-PWR-3]  103.63 165.13 270 bottom
PG4417  GAP-CLOSE-PWR-3-GP  [GAP-CLOSE-PWR-3]  163.57 176.56 180 top
PG4518  -  [GAP-CLOSE-PWR]  49.55 50.4 0 top
PG4520  -  [GAP-CLOSE-PWR]  49.55 49.64 0 top
PG4521  -  [GAP-CLOSE-PWR]  27.73 47.57 180 top
PG4524  -  [GAP-CLOSE-PWR]  27.73 48.33 180 top
PG4525  -  [GAP-CLOSE-PWR]  27.73 49.09 180 top
PG4531  -  [GAP-CLOSE-PWR]  27.73 49.86 180 top
PG4532  GAP-CLOSE-PWR-3-GP  [GAP-CLOSE-PWR-3]  43.17 31.77 0 bottom
PG4534  -  [GAP-CLOSE-PWR]  49.55 48.88 0 top
PG4535  GAP-CLOSE-PWR-3-GP  [GAP-CLOSE-PWR-3]  29.48 31.92 180 bottom
PG4536  -  [GAP-CLOSE-PWR]  49.55 48.11 0 top
PG4542  -  [GAP-CLOSE-PWR]  49.55 47.35 0 top
PG4543  -  [GAP-CLOSE-PWR]  49.55 51.16 0 top
PG4601  GAP-CLOSE-PWR-3-GP  [GAP-CLOSE-PWR-3]  116.79 145.67 90 bottom
PG4707  GAP-CLOSE-PWR-3-GP  [GAP-CLOSE-PWR-3]  123.44 122.71 90 bottom
PG4708  GAP-CLOSE-PWR-3-GP  [GAP-CLOSE-PWR-3]  123.44 120.55 270 bottom
PG4808  GAP-CLOSE-PWR-3-GP  [GAP-CLOSE-PWR-3]  110.87 122.08 90 bottom
PG4809  GAP-CLOSE-PWR-3-GP  [GAP-CLOSE-PWR-3]  110.87 120.04 270 bottom
PG5021  GAP-CLOSE-PWR-3-GP  [GAP-CLOSE-PWR-3]  135.25 122.97 90 bottom
PG5022  GAP-CLOSE-PWR-3-GP  [GAP-CLOSE-PWR-3]  135.25 120.68 270 bottom
PG5023  -  [GAP-CLOSE-PWR]  138.3 134.9 90 bottom
PG5024  -  [GAP-CLOSE-PWR]  139.06 134.9 90 bottom
PG5025  -  [GAP-CLOSE-PWR]  135.09 116.47 90 bottom
PG5026  -  [GAP-CLOSE-PWR]  138.9 116.47 90 bottom
PG5027  -  [GAP-CLOSE-PWR]  138.14 116.47 90 bottom
PG5028  -  [GAP-CLOSE-PWR]  137.38 116.47 90 bottom
PG5029  -  [GAP-CLOSE-PWR]  136.62 116.47 90 bottom
PG5030  -  [GAP-CLOSE-PWR]  135.85 116.47 90 bottom
PG5031  -  [GAP-CLOSE-PWR]  134.33 116.47 90 bottom
PG5101  -  [GAP-CLOSE-PWR]  42.36 21.85 90 top
PG5102  -  [GAP-CLOSE-PWR]  43.12 21.85 90 top
PG5103  -  [GAP-CLOSE-PWR]  55.75 26.83 90 top
PG5104  -  [GAP-CLOSE-PWR]  54.99 26.83 90 top
PG5105  -  [GAP-CLOSE-PWR]  54.22 26.83 90 top
PG5106  -  [GAP-CLOSE-PWR]  53.46 26.83 90 top
PG5107  GAP-CLOSE-PWR-3-GP  [GAP-CLOSE-PWR-3]  72 17.23 180 bottom
PG5124  -  [GAP-CLOSE-PWR]  56.51 26.83 90 top
PG5211  -  [GAP-CLOSE-PWR]  150.14 119.32 180 bottom
PG5212  -  [GAP-CLOSE-PWR]  150.14 118.56 180 bottom
PG5213  -  [GAP-CLOSE-PWR]  150.14 117.79 180 bottom
PG5214  -  [GAP-CLOSE-PWR]  150.14 117.04 180 bottom
PG5301  -  [GAP-CLOSE-PWR]  144.28 116.78 90 bottom
PG5302  -  [GAP-CLOSE-PWR]  145.04 116.78 90 bottom
PG5303  -  [GAP-CLOSE-PWR]  145.8 116.78 90 bottom
PG5304  -  [GAP-CLOSE-PWR]  144.42 139.24 90 bottom
PG5305  -  [GAP-CLOSE-PWR]  146.56 116.78 90 bottom
PG5306  -  [GAP-CLOSE-PWR]  147.33 116.78 90 bottom
PG5307  -  [GAP-CLOSE-PWR]  148.09 116.78 90 bottom
PG5308  -  [GAP-CLOSE-PWR]  145.18 139.24 90 bottom
PG5309  -  [GAP-CLOSE-PWR]  143.66 139.24 90 bottom
PG5310  -  [GAP-CLOSE-PWR]  142.9 139.24 90 bottom
PG5404  -  [GAP-CLOSE-PWR]  36.89 14.47 270 top
PG5405  -  [GAP-CLOSE-PWR]  170.68 102.01 270 bottom
PG5406  -  [GAP-CLOSE-PWR]  169.92 102.01 270 bottom
PG5407  -  [GAP-CLOSE-PWR]  169.16 102.01 270 bottom
PG8301  -  [GAP-CLOSE-PWR]  142.49 158.91 90 bottom
PG8302  -  [GAP-CLOSE-PWR]  143.25 158.91 90 bottom
PG8303  -  [GAP-CLOSE-PWR]  141.73 158.91 90 bottom
PG8304  -  [GAP-CLOSE-PWR]  158.24 156.75 270 bottom
PG8305  -  [GAP-CLOSE-PWR]  157.47 156.75 270 bottom
PG8306  -  [GAP-CLOSE-PWR]  156.71 156.75 270 bottom
PG8307  -  [GAP-CLOSE-PWR]  155.95 156.75 270 bottom
PL4401  COIL-4D7UH-33-GP  [L7066-1830-UH119]  130.02 158.98 270 bottom
PL4501  IND-2D2UH-46-GP-U  [L736630-MH119]  42.96 40.65 180 bottom
PL4502  IND-3D3UH-57GP  [L736630H119]  33.49 40.57 0 bottom
PL4701  COIL-D15UH-2-GP  [L7366-1930H158]  123.44 121.57 180 bottom
PL4801  COIL-D15UH-2-GP  [L7366-1930H158]  110.87 121.06 180 bottom
PL5001  IND-D47UH-22-GP  [L736630H119]  135.25 121.82 180 bottom
PL5101  IND-D47UH-22-GP  [L736630H119]  63.05 21.73 270 bottom
PL5301  IND-D68UH-36-GP-U  [L686647-127318H119]  145.55 128.78 180 bottom
PL8201  IND-D33UH-7-GP  [L736630H119]  215.51 116.11 0 bottom
PL8202  IND-D33UH-7-GP  [L736630H119]  203.45 116.49 0 bottom
PL8301  IND-2D2UH-161-GP-U  [L4240-D815-UH79]  152.01 154.59 270 bottom
PQ4301  DMN5L06K-7-GP  [SOT23DGS2D4H48]  107.82 175.96 180 top
PQ4302  LMBT3904LT1G-GP  [SOT23CBE2D4H44]  114.17 175.67 0 top
PQ4303  2N7002KDW-GP  [SOT-363H44]  117.72 174.4 0 top
PQ4304  PDTC124EU-1-GP  [SOT323CBE2D2H44]  120.9 174.27 180 top
PQ4305  PDTA124EU-1-GP  [SOT323CBE2D2H44]  107.44 171.1 270 top
PQ4306  2N7002KDW-GP  [SOT-363H44]  88.45 158.9 270 bottom
PQ4308  2N7002K-2-GP  [SOT23DGS2D4H44]  114.17 171.86 90 top
PQ4402  2N7002KDW-GP  [SOT-363H44]  103.94 167.15 0 top
PQ4403  2N7002K-2-GP  [SOT23DGS2D4H44]  142.51 155.57 0 top
PQ4405  2N7002KDW-GP  [SOT-363H44]  123.44 170.46 180 top
PQ4408  LMBT3906LT1G-1-GP  [SOT23CBE2D4H44]  115.95 167.67 90 top
PQ8301  2N7002KDW-GP  [SOT-363H44]  179.31 144.79 270 top
PQ8302  2N7002K-2-GP  [SOT23DGS2D4H44]  159.52 37.7 90 top
PQ8303  2N7002KDW-GP  [SOT-363H44]  155.8 38.12 270 top
PQ8304  SIRA06DP-T1-GE3-1-GP  [PPAK-5PH45]  152.63 32.41 90 top
PQ8305  2N7002KDW-GP  [SOT-363H44]  217.42 97.95 90 bottom
PQ8306  2N7002KDW-GP  [SOT-363H44]  169.31 142.7 90 bottom
PQ8307  2N7002KDW-GP  [SOT-363H44]  169.31 139.52 90 bottom
PR4302  15KR2F-GP  [R402H16]  111.76 173.62 0 top
PR4303  10KR2J-3-GP  [R402H16]  111.52 175.84 90 top
PR4304  2K2R2J-2-GP  [R402H16]  122.93 175.04 0 top
PR4305  33R2J-2-GP  [R402H16]  122.93 173.26 180 top
PR4306  33R2J-2-GP  [R402H16]  105.53 175.76 180 top
PR4307  240KR3-GP  [R603H22]  88.48 154.47 90 bottom
PR4308  47KR3J-L-GP  [R603H22]  110.1 171.23 180 top
PR4309  100KR2J-1-GP  [R402H16]  104.48 173.55 90 top
PR4310  0R0402-PAD-2-GP  [0R0402-PAD-1]  116.58 177.07 0 top
PR4311  10KR2J-3-GP  [R402H16]  117.47 177.07 180 top
PR4312  100KR2J-1-GP  [R402H16]  91.11 159.14 90 bottom
PR4313  100KR2J-1-GP  [R402H16]  91.11 160.03 270 bottom
PR4314  3K3R6J-GP  [R1206H28]  88.45 156.24 90 bottom
PR4315  1KR2J-1-GP  [R402H16]  117.47 171.23 180 top
PR4316  100KR2J-1-GP  [R402H16]  118.36 171.23 0 top
PR4317  0R0603-PAD-1-GP-U  [0R0603-PAD-U]  102.21 172.32 180 top
PR4318  100KR2J-1-GP  [R402H16]  118.36 177.07 180 top
PR4319  0R0402-PAD-2-GP  [0R0402-PAD-1]  110.98 170.59 270 bottom
PR4402  D01R3721F-GP-U  [R3720H40]  105.3 151.53 90 top
PR4403  100KR2J-1-GP  [R402H16]  102.15 154.67 270 top
PR4404  0R2J-2-GP  [R402H16]  109.85 156.67 90 bottom
PR4405  3KR5J-GP  [R805H24]  106.93 168.56 270 top
PR4406  10KR2F-2-GP  [R402H16]  103.99 169.42 270 top
PR4407  10R2J-2-GP  [R402H14]  112.95 157.64 90 bottom
PR4408  309KR2F-GP  [R402H16]  104.81 155.59 180 bottom
PR4409  47KR2F-GP  [R402H16]  106.59 155.59 180 bottom
PR4410  4K02R2F-GP  [R402H16]  108.36 155.59 0 bottom
PR4411  3K3R2J-3-GP  [R402H16]  98.26 165.86 180 bottom
PR4412  3K3R2J-3-GP  [R402H16]  99.15 165.86 180 bottom
PR4413  100KR2F-L1-GP  [R402H16]  122.68 168.18 90 top
PR4414  10R2F-L-GP  [R402H14]  106.29 165.26 0 bottom
PR4415  D01R3721F-GP-U  [R3720H40]  132.84 165.13 180 top
PR4416  0R0402-PAD-2-GP  [0R0402-PAD-1]  107.48 155.59 0 bottom
PR4417  10R2F-L-GP  [R402H14]  108.07 165.26 0 bottom
PR4418  0R0402-PAD-2-GP  [0R0402-PAD-1]  100.07 159.54 270 bottom
PR4419  7D5R2F-GP  [R402H16]  107.18 165.26 0 bottom
PR4420  100KR2J-1-GP  [R402H16]  101.72 163.61 270 bottom
PR4421  59KR2F-GP  [R402H16]  101.75 162.69 270 bottom
PR4422  20KR3J-1-GP  [R603H22]  136.24 155.18 180 top
PR4423  59KR2F-GP  [R402H16]  101.72 164.49 90 bottom
PR4424  10KR2F-2-GP  [R402H16]  101.75 161.85 90 bottom
PR4425  30KR2F-GP  [R402H16]  99.1 158.18 90 bottom
PR4430  470KR2F-GP  [R402H16]  135.5 154.59 90 bottom
PR4431  100KR2J-1-GP  [R402H16]  118.87 167.92 270 top
PR4432  120KR2J-GP  [R402H16]  110.74 165.64 270 top
PR4433  1MR2J-1-GP  [R402H16]  118.87 168.81 90 top
PR4435  100KR2J-1-GP  [R402H16]  110.74 164.75 90 top
PR4450  10KR2F-2-GP  [R402H16]  124.45 168.18 90 top
PR4451  680KR2F-GP  [R402H16]  113.53 168.69 180 top
PR4455  0R0402-PAD-2-GP  [0R0402-PAD-1]  121.41 170.59 0 top
PR4458  0R0402-PAD-2-GP  [0R0402-PAD-1]  120.9 168.05 270 top
PR4462  0R0402-PAD-2-GP  [0R0402-PAD-1]  113.53 166.91 180 top
PR4463  0R2J-2-GP  [R402H16]  112.52 165.64 270 top
PR4501  0R2J-2-GP  [R402H16]  33.9 59.97 270 top
PR4504  0R0402-PAD-2-GP  [0R0402-PAD-1]  43.17 59.2 0 top
PR4506  0R0402-PAD-2-GP  [0R0402-PAD-1]  34.82 56.44 90 top
PR4507  0R0402-PAD-2-GP  [0R0402-PAD-1]  34.16 57.81 180 top
PR4512  6K8R2F-2-GP  [R402H16]  36.6 59.94 0 top
PR4517  174KR2F-GP  [R402H16]  35 57.81 180 top
PR4523  10KR2F-2-GP  [R402H16]  37.46 59.08 180 top
PR4524  1D5R3-GP  [R603H22]  44.06 53.62 90 top
PR4525  0R2J-2-GP  [R402H16]  41.4 59.2 0 top
PR4526  9K76R2F-1-GP  [R402H16]  40.13 60.55 90 top
PR4527  15K4R2F-GP  [R402H16]  40.13 59.59 270 top
PR4528  1D5R3-GP  [R603H22]  33.9 53.11 90 top
PR4529  2D2R5F-2-GP  [R805H24]  39.81 41.53 180 top
PR4530  0R2J-2-GP  [R402H16]  33.9 59.08 90 top
PR4531  137KR2F-1-GP  [R402H16]  42.29 59.2 180 top
PR4532  0R0402-PAD-2-GP  [0R0402-PAD-1]  38.99 58.56 90 bottom
PR4533  2D2R5F-2-GP  [R805H24]  37.98 41.53 180 top
PR4534  100KR2J-1-GP  [R402H16]  34.82 55.55 90 top
PR4535  0R2J-2-GP  [R402H16]  36.09 61.21 270 top
PR4601  1KR2F-3-GP  [R402H16]  110.3 138.63 180 top
PR4602  750R2F-GP  [R402H16]  114.04 150.64 270 top
PR4603  1KR2F-3-GP  [R402H16]  107.5 142.24 90 top
PR4604  0R0402-PAD-2-GP  [0R0402-PAD-1]  112.34 151.95 0 top
PR4605  825R2F-GP  [R402H16]  112.9 149.38 0 top
PR4606  NTC-100K-11-GP-U  [NTC-402H24-U]  139.69 125.25 180 bottom
PR4607  0R0402-PAD-2-GP  [0R0402-PAD-1]  111.47 151.95 0 top
PR4608  2K74R2F-GP  [R402H16]  111.15 149.37 0 top
PR4609  14K3R2F-GP  [R402H16]  116.84 150.35 270 top
PR4611  48D7KR2F-GP  [R402H16]  114.52 149.38 180 top
PR4612  8K06R3F-AS-GP  [R603H22]  116.72 151.95 270 top
PR4613  102KR2F-GP  [R402H16]  115.07 145.39 180 bottom
PR4614  10KR2F-2-GP  [R402H16]  118.61 150.88 270 top
PR4616  2K49R2F-GP  [R402H16]  110.64 151.21 0 top
PR4617  0R0402-PAD-2-GP  [0R0402-PAD-1]  105.8 148.58 90 top
PR4618  0R0402-PAD-2-GP  [0R0402-PAD-1]  105.8 147.74 90 top
PR4619  1KR2F-3-GP  [R402H16]  107.67 147.25 270 top
PR4621  45D3R2F-L-GP  [R402H16]  122.8 147.76 90 bottom
PR4622  75R2F-2-GP  [R402H16]  122.8 146.92 90 bottom
PR4623  100R2F-L1-GP-U  [R402H14]  122.8 146.08 270 top
PR4624  1KR2F-3-GP  [R402H16]  122.8 146.08 90 bottom
PR4625  37D4R2F-GP  [R402H16]  106.67 145.7 90 bottom
PR4626  1KR2F-3-GP  [R402H16]  107.94 145.19 180 bottom
PR4627  8K06R3F-AS-GP  [R603H22]  123.57 144.09 90 top
PR4628  107KR2F-GP  [R402H16]  117.15 144.53 90 bottom
PR4629  14KR2F-GP  [R402H16]  122.8 145.19 90 top
PR4630  0R0402-PAD-2-GP  [0R0402-PAD-1]  118.99 149.61 180 top
PR4631  4K75R2F-1-GP  [R402H16]  106.17 144.43 180 bottom
PR4632  24K9R2F-L-GP  [R402H16]  111.36 144.12 90 bottom
PR4633  NTC-100K-11-GP-U  [NTC-402H24-U]  127.88 122.33 180 bottom
PR4634  NTC-220K-5-GP-U  [NTC-402H24-U]  106.45 123.5 180 bottom
PR4635  61K9R2F-GP  [R402H16]  119.81 142.76 270 bottom
PR4636  2K49R2F-GP  [R402H16]  121.2 142.32 0 bottom
PR4637  57K6R3F-2-GP  [R603H22]  104.19 142.09 270 bottom
PR4638  200KR2F-L-GP  [R402H16]  105.79 143.16 90 top
PR4639  75KR2F-GP  [R402H16]  106.19 144.43 180 top
PR4640  12K4R2F-GP  [R402H16]  107.04 145.18 180 top
PR4644  422R2F-2-GP  [R402H16]  120.06 141.05 90 top
PR4645  0R0402-PAD-2-GP  [0R0402-PAD-1]  121.74 140.16 270 top
PR4646  10R2F-L-GP  [R402H14]  106.74 141.99 90 bottom
PR4647  3K4R2F-GP  [R402H16]  119.25 139.37 90 top
PR4648  0R0402-PAD-2-GP  [0R0402-PAD-1]  121.74 139.34 270 top
PR4649  2K49R2F-GP  [R402H16]  119.25 138.56 90 top
PR4650  0R0402-PAD-2-GP  [0R0402-PAD-1]  116.91 138.41 180 top
PR4651  4K87R2F-GP  [R402H16]  106.74 141.16 270 bottom
PR4652  12K7R2F-GP  [R402H16]  117.8 138.41 180 top
PR4653  NTC-100K-11-GP-U  [NTC-402H24-U]  129.2 128.82 180 bottom
PR4655  0R0402-PAD-2-GP  [0R0402-PAD-1]  107.49 141.41 90 top
PR4656  NTC-100K-11-GP-U  [NTC-402H24-U]  115.47 127 0 bottom
PR4657  2D2R2F-GP  [R402H16]  111.37 137.72 180 top
PR4658  90K9R2F-GP  [R402H16]  114.54 141.01 0 bottom
PR4659  24KR2F-GP  [R402H16]  112.87 141.11 0 bottom
PR4660  18K7R2F-GP  [R402H16]  115.36 141.02 0 bottom
PR4661  12K7R2F-GP  [R402H16]  107.49 140.58 90 top
PR4662  49K9R2F-L-GP  [R402H16]  113.7 141.02 0 bottom
PR4663  10KR2F-2-GP  [R402H16]  116.19 140.64 0 bottom
PR4664  24KR2F-GP  [R402H16]  111.98 141.11 0 bottom
PR4665  49D9R2F-GP  [R402H16]  120.14 147.86 270 top
PR4666  0R2J-2-GP  [R402H16]  120.14 146.97 270 top
PR4667  10R2F-L-GP  [R402H14]  120.54 145.7 0 top
PR4668  100R2F-L1-GP-U  [R402H14]  120.06 144.4 90 top
PR4669  75R2F-2-GP  [R402H16]  122.8 145.19 90 bottom
PR4670  0R0402-PAD-2-GP  [0R0402-PAD-1]  118.1 149.61 180 top
PR4671  0R0402-PAD-2-GP  [0R0402-PAD-1]  111.34 145.81 270 bottom
PR4701  3D9R3-GP  [R603H22]  126.69 131.78 0 top
PR4702  2D2R2F-GP  [R402H16]  127.33 127.53 270 top
PR4703  2D2R5F-2-GP  [R805H24]  121.25 125.3 180 top
PR4704  0R0402-PAD-2-GP  [0R0402-PAD-1]  128.3 130.61 180 bottom
PR4802  3D9R3-GP  [R603H22]  113.33 131.27 0 top
PR4803  2D2R2F-GP  [R402H16]  114.11 126.89 270 top
PR4804  2D2R5F-2-GP  [R805H24]  108.07 124.36 180 top
PR4808  0R0402-PAD-2-GP  [0R0402-PAD-1]  115.76 129.98 180 bottom
PR5013  2D2R3-1-U-GP  [R603H22]  137.02 137.42 0 top
PR5014  2D2R5F-2-GP  [R805H24]  132.71 127.41 180 top
PR5101  30K1R2F-L-GP  [R402H16]  49.31 17.16 0 top
PR5102  182KR2F-GP  [R402H16]  47 26.42 180 top
PR5103  10KR2F-2-GP  [R402H16]  47.62 18.43 90 top
PR5104  20KR2F-L-GP  [R402H16]  45.25 26.57 0 top
PR5105  2D2R3-1-U-GP  [R603H22]  52.54 24.13 90 top
PR5106  0R0402-PAD-2-GP  [0R0402-PAD-1]  51.85 16.73 90 top
PR5107  0R0402-PAD-2-GP  [0R0402-PAD-1]  50.79 25.82 0 top
PR5108  12KR2F-L-GP  [R402H16]  46.08 26.58 180 top
PR5109  0R0402-PAD-2-GP  [0R0402-PAD-1]  47.97 26.56 180 top
PR5110  0R2J-2-GP  [R402H16]  48.8 26.57 180 top
PR5111  0R0603-PAD-2-GP-U  [0R0603-PAD-1-U]  44.79 18.28 270 top
PR5112  2D2R5F-2-GP  [R805H24]  60.45 16.67 270 top
PR5216  0R2J-2-GP  [R402H16]  151.12 125.38 90 bottom
PR5218  0R2J-2-GP  [R402H16]  151.12 126.27 90 bottom
PR5301  68KR2F-GP  [R402H16]  151.38 136.73 90 bottom
PR5302  0R0603-PAD-2-GP-U  [0R0603-PAD-1-U]  147.09 136.7 0 top
PR5303  0R0402-PAD-2-GP  [0R0402-PAD-1]  147.54 138.62 0 bottom
PR5304  100KR2F-L1-GP  [R402H16]  153.92 135.46 90 bottom
PR5305  100KR2F-L1-GP  [R402H16]  150.11 136.35 0 bottom
PR5307  1MR2J-1-GP  [R402H16]  152.4 133.15 180 bottom
PR5308  0R0402-PAD-2-GP  [0R0402-PAD-1]  150.49 134.95 90 bottom
PR5309  0R2J-2-GP  [R402H16]  153.67 132.77 90 bottom
PR5310  0R0402-PAD-2-GP  [0R0402-PAD-1]  153.92 134.57 90 bottom
PR5311  0R2J-2-GP  [R402H16]  153.67 133.66 90 bottom
PR5401  47KR2J-2-GP  [R402H16]  174.49 113.06 270 bottom
PR5402  100KR2F-L1-GP  [R402H16]  172.71 112.17 270 bottom
PR5403  16K5R2F-2-GP  [R402H16]  172.21 102.9 270 bottom
PR5404  13K3R2F-L1-GP  [R402H16]  173.98 102.9 270 bottom
PR5405  0R2J-2-GP  [R402H16]  42.35 19.02 270 top
PR5406  0R2J-2-GP  [R402H16]  173.61 114.36 180 bottom
PR5407  0R2J-2-GP  [R402H16]  174.48 114.36 180 bottom
PR5408  0R0402-PAD-2-GP  [0R0402-PAD-1]  172.71 113.06 90 bottom
PR8201  499KR2F-1-GP  [R402H16]  207.56 94.24 0 bottom
PR8202  2D2R2F-GP  [R402H16]  207.51 92.49 0 bottom
PR8203  100KR2J-1-GP  [R402H16]  203.88 96.91 270 bottom
PR8206  20KR2F-L-GP  [R402H16]  211.95 92.6 0 bottom
PR8207  0R2J-2-GP  [R402H16]  213.23 93.33 90 bottom
PR8208  2KR2F-3-GP  [R402H16]  209.82 94.59 270 bottom
PR8209  18KR2F-GP  [R402H16]  210.23 93.32 180 bottom
PR8210  0R3J-0-U-GP  [R603H22]  213.47 99.05 270 bottom
PR8211  0R3J-0-U-GP  [R603H22]  203.88 98.05 90 bottom
PR8212  100R2F-L1-GP-U  [R402H14]  202.74 95.64 180 bottom
PR8213  100R2F-L1-GP-U  [R402H14]  202.74 93.86 180 bottom
PR8215  2D2R5F-2-GP  [R805H24]  208.4 111.92 180 bottom
PR8216  2D2R5F-2-GP  [R805H24]  210.31 111.92 180 bottom
PR8220  0R2J-2-GP  [R402H16]  201.47 94.24 90 bottom
